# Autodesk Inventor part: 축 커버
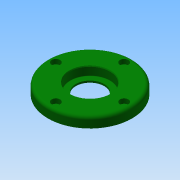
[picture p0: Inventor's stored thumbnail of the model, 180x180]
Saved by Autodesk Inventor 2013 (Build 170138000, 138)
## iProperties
Created: 2015-10
Part Number: 축 커버
Document SubType Name: Modeling
Designer: mdu
Density: 2.71 g/cm^3
Material: 알루미늄 6061
Mass: 110.828 g
Surface Area: 134.096 cm^2
Volume: 40.896 cm^3
Author: mdu
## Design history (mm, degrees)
sketch "스케치1"
  geometry: C1 r 40 at (0, 0) reference; C2 r 26 at (0, 0) reference; 1 further point
  node "참조1"
  node "참조2"
extrude "돌출1" new body sketch "스케치1" distance "d0" = 10; taper "d1" = 0 deg
extrude "돌출2" join sketch "스케치1" distance "d2" = 3; taper "d3" = 0 deg
hole "구멍1" diameter "d6" = 27; stored, may be unused: countersink angle "d10" = 90 deg, drill point angle "d12" = 118 deg; dims "d7" = 6, "d8" = 38, "d9" = 8.3, "d11" = 8, "d33" = 10, "d34" = 10
sketch "스케치2"
  geometry: C1 r 20 at (0, 0); 1 further point
  constraints: 1 centre point, 1 coincident
  dimensions: "d13" = 40 diameter of C1
extrude "돌출3" cut sketch "스케치2" distance "d14" = 3; taper "d15" = 0 deg
sketch "스케치3"
  geometry: C1 r 1.621 at (0, 32.5) reference; 1 further point
hole "구멍2" sketch "스케치3" at (0, 32.5) diameter "d16" = 4.5; stored, may be unused: countersink angle "d20" = 90 deg, drill point angle "d22" = 118 deg; dims "d17" = 6, "d18" = 8, "d19" = 4.4, "d21" = 8
fillet "모깎기1" dims "d26" = 3, "d27" = 0.3
chamfer "모따기1" distance "d28" = 1; stored, may be unused: second distance "d29" = 2, angle "d30" = 45 deg
chamfer "모따기2" distance "d31" = 0.8; stored, may be unused: second distance "d32" = 2, angle "d35" = 30 deg
node "솔리드1"
pattern_circular "원형 패턴1" dims angle "d24" = 360 deg
node "참조3"
